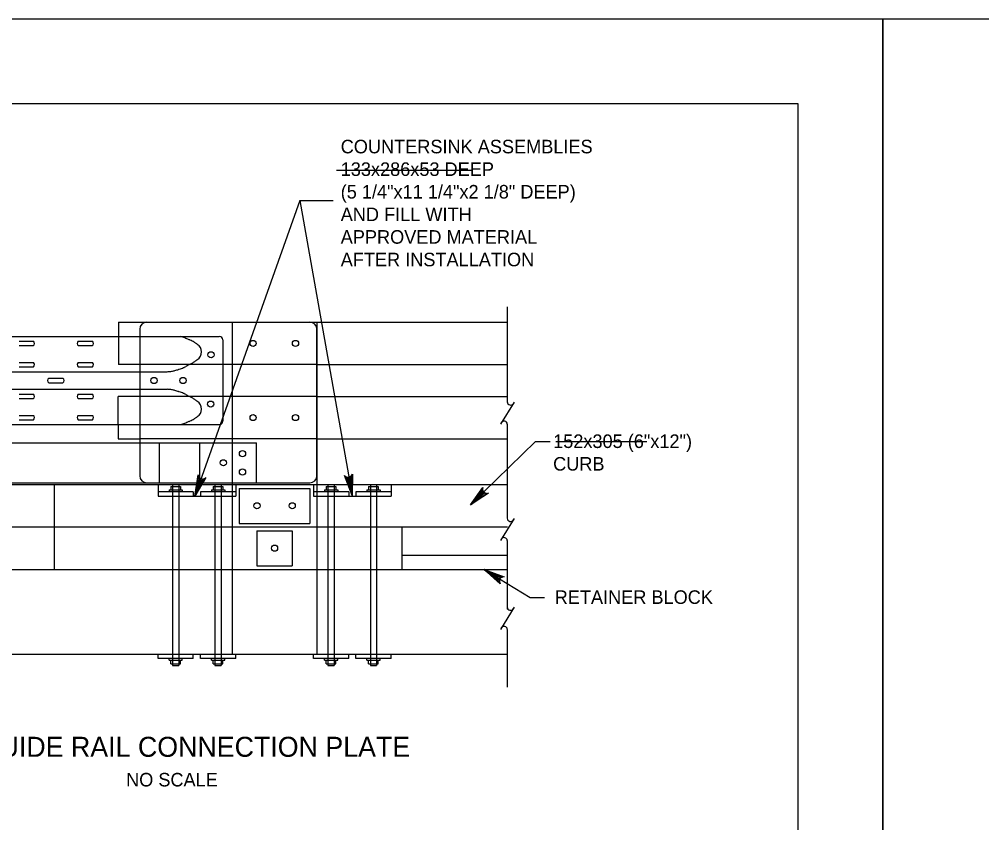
# Model space of a CAD drawing. Extents: x 179 to 454, y -271 to 54.
# Drawn here: x 387.12 to 395.64, y -7.11 to 0 of the extents above; entities that cross this region are included whole.
import ezdxf

# ---------------------------------------------------------------- set-up
doc = ezdxf.new("R2010")
doc.units = 0
for name, color, linetype in [('Level 1', 7, 'Continuous'), ('Level 2', 7, 'Continuous'), ('Level 3', 7, 'Continuous'), ('Level 41', 7, 'Continuous'), ('Level 52', 7, 'Continuous'), ('Level 62', 7, 'Continuous'), ('Level 63', 7, 'Continuous')]:
    doc.layers.add(name, color=color, linetype=linetype)

msp = doc.modelspace()

# ---------------------------------------------------------------- linework, layer by layer
at = {"layer": 'Level 1'}
msp.add_lwpolyline([(362.5132, -21.25), (394.0132, -21.25), (394.0132, -0.75), (362.5132, -0.75)], close=True, dxfattribs=at)
at = {"layer": 'Level 2'}
for p, q in [((391.4403, -2.5474), (391.4403, -3.3866)), ((388.0011, -2.6827), (390.048, -2.6827)), ((389.0062, -2.6827), (389.0062, -3.0577)), ((389.7562, -2.6827), (389.7562, -3.0577)), ((390.048, -2.6827), (391.4422, -2.6827)), ((387.0486, -2.8077), (388.8923, -2.8077)), ((388.001, -2.8077), (388.001, -3.0577)), ((388.1886, -2.7452), (388.1886, -3.5889)), ((387.1222, -2.8507), (387.2472, -2.8507)), ((387.1222, -2.8897), (387.2472, -2.8897)), ((387.6443, -2.8507), (387.7693, -2.8507)), ((387.6443, -2.8897), (387.7693, -2.8897)), ((388.9236, -2.839), (388.9236, -3.5577)), ((387.1222, -3.0382), (387.2472, -3.0382)), ((387.6443, -3.0382), (387.7693, -3.0382)), ((389.7562, -3.0577), (388.001, -3.0577)), ((389.0062, -3.0577), (389.0062, -3.3389)), ((389.7562, -3.0577), (389.7562, -3.3389)), ((389.7562, -3.0577), (391.4422, -3.0577)), ((385.5172, -3.1202), (388.4303, -3.1202)), ((387.1222, -3.0772), (387.2472, -3.0772)), ((387.6443, -3.0772), (387.7693, -3.0772)), ((387.3827, -3.1788), (387.5077, -3.1788)), ((387.3827, -3.2178), (387.5077, -3.2178)), ((385.4967, -3.2764), (388.4303, -3.2764)), ((387.1222, -3.3194), (387.2472, -3.3194)), ((387.6443, -3.3194), (387.7693, -3.3194)), ((387.1222, -3.3585), (387.2472, -3.3585)), ((387.6443, -3.3585), (387.7693, -3.3585)), ((389.7562, -3.3389), (387.9967, -3.3389)), ((387.9967, -3.5889), (387.9967, -3.3389)), ((389.0062, -3.3389), (389.0062, -3.7139)), ((389.7562, -3.3389), (389.7562, -3.7139)), ((389.7562, -3.3389), (391.4422, -3.3389)), ((391.5017, -3.3888), (391.3789, -3.5844)), ((387.1222, -3.5069), (387.2472, -3.5069)), ((387.1222, -3.546), (387.2472, -3.546)), ((387.6443, -3.5069), (387.7693, -3.5069)), ((387.6443, -3.546), (387.7693, -3.546)), ((385.4967, -3.5889), (388.8923, -3.5889)), ((387.9967, -3.5889), (387.9967, -3.7139)), ((388.1886, -3.5889), (388.1886, -4.0414)), ((391.4403, -3.584), (391.4403, -4.4181)), ((387.9967, -3.7139), (388.1886, -3.7139)), ((389.7562, -3.7139), (388.1885, -3.7139)), ((389.0062, -3.7139), (389.0062, -4.2217)), ((389.7562, -3.7139), (389.7562, -4.2217)), ((389.7562, -3.7139), (391.4422, -3.7139)), ((385.2677, -3.7502), (389.2222, -3.7502)), ((389.7562, -3.9997), (389.7562, -4.1202)), ((385.2677, -4.1039), (389.6937, -4.1039)), ((386.2928, -4.1202), (391.4422, -4.1202)), ((387.4317, -4.1202), (387.4317, -4.8702)), ((387.5406, -4.1202), (391.222, -4.1202)), ((388.3499, -4.1202), (388.3499, -4.2217)), ((388.4476, -4.167), (388.4476, -4.1827)), ((388.4476, -4.167), (388.5648, -4.167)), ((388.4632, -4.1357), (388.4632, -4.167)), ((388.4632, -4.1357), (388.5492, -4.1357)), ((388.4788, -4.1202), (388.5335, -4.1202)), ((388.4788, -4.1202), (388.4788, -5.7217)), ((388.5335, -4.1202), (388.5335, -5.7217)), ((388.5492, -4.1357), (388.5492, -4.167)), ((388.5648, -4.167), (388.5648, -4.1827)), ((388.8226, -4.167), (388.8226, -4.1827)), ((388.8226, -4.167), (388.9398, -4.167)), ((388.8382, -4.1357), (388.9242, -4.1357)), ((388.8382, -4.1357), (388.8382, -4.167)), ((388.8538, -4.1202), (388.9085, -4.1202)), ((388.8538, -4.1202), (388.8538, -5.7217)), ((388.9085, -4.1202), (388.9085, -5.7217)), ((388.9242, -4.1357), (388.9242, -4.167)), ((388.9398, -4.167), (388.9398, -4.1827)), ((389.0062, -4.1039), (389.0062, -4.1202)), ((389.0374, -4.1202), (389.0374, -4.2217)), ((389.0687, -4.1537), (389.6937, -4.1537)), ((389.0687, -4.1537), (389.0687, -4.4639)), ((389.0687, -4.1538), (389.6937, -4.1538)), ((389.6937, -4.1537), (389.6937, -4.4639)), ((389.7249, -4.1202), (389.7249, -4.2217)), ((389.7562, -4.1039), (389.7562, -4.1697)), ((389.8226, -4.167), (389.8226, -4.1827)), ((389.8226, -4.167), (389.9398, -4.167)), ((389.8382, -4.1357), (389.9242, -4.1357)), ((389.8382, -4.1357), (389.8382, -4.167)), ((389.8538, -4.1202), (389.9085, -4.1202)), ((389.8538, -4.1202), (389.8538, -5.7217)), ((389.9085, -4.1202), (389.9085, -5.7217)), ((389.9242, -4.1357), (389.9242, -4.167)), ((389.9398, -4.167), (389.9398, -4.1827)), ((390.1976, -4.167), (390.1976, -4.1827)), ((390.1976, -4.167), (390.3148, -4.167)), ((390.2132, -4.1357), (390.2992, -4.1357)), ((390.2132, -4.1357), (390.2132, -4.167)), ((390.2288, -4.1202), (390.2835, -4.1202)), ((390.2288, -4.1202), (390.2288, -5.7217)), ((390.2835, -4.1202), (390.2835, -5.7217)), ((390.2992, -4.1357), (390.2992, -4.167)), ((390.3148, -4.167), (390.3148, -4.1827)), ((390.4124, -4.1202), (390.4124, -4.2217)), ((388.6624, -4.1827), (388.3499, -4.1827)), ((388.3499, -4.2217), (389.0374, -4.2217)), ((388.6624, -4.1827), (388.6624, -4.2217)), ((389.0374, -4.1827), (388.7249, -4.1827)), ((388.7249, -4.1827), (388.7249, -4.2217)), ((389.0062, -4.2217), (389.0062, -5.6201)), ((390.0374, -4.1827), (389.7249, -4.1827)), ((389.7249, -4.2217), (390.4124, -4.2217)), ((389.7562, -4.2217), (389.7562, -5.6201)), ((390.0374, -4.1827), (390.0374, -4.2217)), ((390.4124, -4.1827), (390.0999, -4.1827)), ((390.0999, -4.1827), (390.0999, -4.2217)), ((391.5017, -4.4203), (391.3789, -4.6159)), ((386.2928, -4.4952), (391.4422, -4.4952)), ((389.0687, -4.4639), (389.6937, -4.4639)), ((390.5062, -4.4952), (390.5062, -4.8702)), ((389.225, -4.5287), (389.225, -4.8389)), ((389.225, -4.5287), (389.5375, -4.5287)), ((389.5375, -4.5287), (389.5375, -4.8389)), ((391.4403, -4.6156), (391.4403, -5.2228)), ((390.5062, -4.7452), (391.4422, -4.7452)), ((389.225, -4.8389), (389.5375, -4.8389)), ((386.2928, -4.8702), (391.4422, -4.8702)), ((391.5017, -5.2059), (391.3789, -5.4015)), ((391.4403, -5.4023), (391.4403, -5.9131)), ((386.2928, -5.6201), (391.4422, -5.6201)), ((388.3499, -5.6592), (388.3499, -5.6201)), ((388.6624, -5.6592), (388.6624, -5.6201)), ((388.7249, -5.6592), (388.7249, -5.6201)), ((389.0374, -5.6592), (389.0374, -5.6201)), ((389.7249, -5.6592), (389.7249, -5.6201)), ((390.0374, -5.6592), (390.0374, -5.6201)), ((390.0999, -5.6592), (390.0999, -5.6201)), ((390.4124, -5.6592), (390.4124, -5.6201)), ((388.6624, -5.6592), (388.3499, -5.6592)), ((388.4476, -5.6748), (388.4476, -5.6592)), ((388.4476, -5.6748), (388.5648, -5.6748)), ((388.4632, -5.7061), (388.4632, -5.6748)), ((388.5492, -5.7061), (388.5492, -5.6748)), ((388.5648, -5.6748), (388.5648, -5.6592)), ((389.0374, -5.6592), (388.7249, -5.6592)), ((388.8226, -5.6748), (388.8226, -5.6592)), ((388.8226, -5.6748), (388.9398, -5.6748)), ((388.8382, -5.7061), (388.8382, -5.6748)), ((388.9242, -5.7061), (388.9242, -5.6748)), ((388.9398, -5.6748), (388.9398, -5.6592)), ((390.0374, -5.6592), (389.7249, -5.6592)), ((389.8226, -5.6748), (389.8226, -5.6592)), ((389.8226, -5.6748), (389.9398, -5.6748)), ((389.8382, -5.7061), (389.8382, -5.6748)), ((389.9242, -5.7061), (389.9242, -5.6748)), ((389.9398, -5.6748), (389.9398, -5.6592)), ((390.4124, -5.6592), (390.0999, -5.6592)), ((390.1976, -5.6748), (390.1976, -5.6592)), ((390.1976, -5.6748), (390.3148, -5.6748)), ((390.2132, -5.7061), (390.2132, -5.6748)), ((390.2992, -5.7061), (390.2992, -5.6748)), ((390.3148, -5.6748), (390.3148, -5.6592)), ((388.4632, -5.7061), (388.5492, -5.7061)), ((388.4788, -5.7217), (388.5335, -5.7217)), ((388.8382, -5.7061), (388.9242, -5.7061)), ((388.8538, -5.7217), (388.9085, -5.7217)), ((389.8382, -5.7061), (389.9242, -5.7061)), ((389.8538, -5.7217), (389.9085, -5.7217)), ((390.2132, -5.7061), (390.2992, -5.7061)), ((390.2288, -5.7217), (390.2835, -5.7217))]:
    msp.add_line(p, q, dxfattribs=at)
for centre in [(389.1912, -2.8702), (389.5663, -2.8702), (388.8193, -2.9709), (388.314, -3.1983), (388.571, -3.1983), (388.8162, -3.4071), (389.1912, -3.5265), (389.5663, -3.5265), (389.0974, -3.8464), (388.9283, -3.927), (389.0974, -4.0077), (389.225, -4.3076), (389.5375, -4.3076), (389.3812, -4.6826)]:
    msp.add_circle(centre, 0.0273, dxfattribs=at)
for centre, radius, start, end in [((388.251, -2.7452), 0.0625, 90, 180), ((388.2969, -3.6302), 0.8602, 71.50655, 72.97663), ((388.8923, -2.839), 0.0312, 0, 90), ((387.2355, -2.8702), 0.0228, 300.85592, 59.14408), ((387.656, -2.8702), 0.0228, 120.85592, 239.14408), ((387.7576, -2.8702), 0.0228, 300.85592, 59.14408), ((388.5192, -2.9656), 0.1594, 68.09066, 71.50655), ((386.536, -7.8966), 5.4742, 67.68511, 68.09066), ((388.4241, -3.2963), 0.5016, 66.34532, 67.68511), ((388.5434, -3.0241), 0.2044, 63.42506, 66.34532), ((387.4315, -5.2469), 2.6898, 62.62019, 63.42506), ((388.6313, -2.9302), 0.0808, 54.67713, 62.62019), ((388.4621, -3.169), 0.3735, 50.98486, 54.67712), ((388.6581, -2.9456), 0.0775, 301.3851, 59.64679), ((387.2355, -3.0577), 0.0228, 300.85592, 59.14408), ((387.656, -3.0577), 0.0228, 120.85592, 239.14408), ((387.7576, -3.0577), 0.0228, 300.85592, 59.14408), ((393.2769, -11.608), 9.733, 118.56505, 118.75012), ((393.7331, -12.4459), 10.6871, 118.47252, 118.56505), ((372.799, 26.154), 33.224, 298.47252, 298.525), ((388.621, -2.9561), 0.092, 298.525, 306.88177), ((388.4254, -2.6954), 0.4179, 306.88177, 310.79926), ((388.4106, -2.6951), 0.4255, 272.64288, 278.36698), ((388.446, -2.9355), 0.1825, 278.36698, 287.11147), ((386.2113, 4.3233), 7.7775, 287.11147, 287.36106), ((388.4527, -2.8462), 0.2658, 287.36106, 288.71113), ((388.0449, -1.6421), 1.5372, 288.71113, 290.23288), ((388.5576, -3.0333), 0.0545, 290.23288, 298.32146), ((387.7228, -1.4842), 1.8143, 298.32146, 298.75012), ((387.3943, -3.1983), 0.0228, 120.85592, 239.14408), ((387.496, -3.1983), 0.0228, 300.85592, 59.14408), ((387.2355, -3.339), 0.0228, 300.85592, 59.14408), ((387.656, -3.339), 0.0228, 120.85592, 239.14408), ((387.7576, -3.339), 0.0228, 300.85592, 59.14408), ((388.4106, -3.7015), 0.4255, 81.63302, 87.35713), ((388.446, -3.4611), 0.1825, 72.88853, 81.63302), ((386.2113, -10.7199), 7.7775, 72.63894, 72.88853), ((388.4527, -3.5504), 0.2658, 71.28887, 72.63894), ((388.0449, -4.7546), 1.5372, 69.76712, 71.28887), ((388.5576, -3.3634), 0.0545, 61.67854, 69.76712), ((387.7228, -4.9125), 1.8143, 61.24988, 61.67854), ((393.2769, 5.2113), 9.733, 241.24988, 241.43495), ((393.7331, 6.0493), 10.6871, 241.43495, 241.52748), ((372.799, -32.5506), 33.224, 61.475, 61.52748), ((388.621, -3.4405), 0.092, 53.11823, 61.475), ((388.4254, -3.7012), 0.4179, 49.20074, 53.11823), ((388.6581, -3.451), 0.0775, 300.35321, 58.61491), ((391.4691, -3.3866), 0.0289, 180, 330), ((387.2355, -3.5265), 0.0228, 300.85592, 59.14408), ((387.656, -3.5265), 0.0228, 120.85592, 239.14408), ((387.7576, -3.5265), 0.0228, 300.85592, 59.14408), ((386.536, 1.4999), 5.4742, 291.90934, 292.31489), ((388.4241, -3.1003), 0.5016, 292.31489, 293.65468), ((388.5434, -3.3726), 0.2044, 293.65468, 296.57494), ((387.4315, -1.1498), 2.6898, 296.57494, 297.37981), ((388.6313, -3.4665), 0.0808, 297.37981, 305.32288), ((388.4621, -3.2276), 0.3735, 305.32288, 309.01514), ((388.8923, -3.5577), 0.0312, 270, 0), ((391.4115, -3.5867), 0.0289, 5.32859, 147.86724), ((388.2969, -2.7665), 0.8602, 287.02337, 288.49345), ((388.5192, -3.4311), 0.1594, 288.49345, 291.90934), ((388.251, -4.0414), 0.0625, 180, 270), ((389.6937, -4.0414), 0.0625, 270, 0), ((391.4691, -4.4181), 0.0289, 180, 330), ((391.4115, -4.6182), 0.0289, 5.32859, 147.86724), ((391.4691, -5.2037), 0.0289, 180, 330), ((391.4115, -5.4037), 0.0289, 5.32859, 147.86724)]:
    msp.add_arc(centre, radius, start, end, dxfattribs=at)
at = {"layer": 'Level 3'}
for p, q in [((389.6041, -1.606), (388.6769, -4.2217)), ((389.6041, -1.606), (389.8982, -1.606)), ((389.6041, -1.606), (390.0679, -4.2164)), ((388.0011, -2.6827), (388.0011, -2.8077)), ((389.7562, -4.0414), (389.7562, -2.7452)), ((388.3642, -4.1039), (388.3642, -3.7502)), ((388.7209, -4.1039), (388.7209, -3.7502)), ((389.2222, -4.1039), (389.2222, -3.7502))]:
    msp.add_line(p, q, dxfattribs=at)
for points in [[(388.677, -4.2217), (388.7063, -4.0343), (388.7109, -4.0512), (388.7202, -4.0623), (388.7312, -4.0685), (388.7437, -4.0707), (388.758, -4.0678), (388.7722, -4.0577), (388.677, -4.2217), (388.758, -4.0678), (388.7437, -4.0707), (388.677, -4.2217), (388.7312, -4.0685), (388.7202, -4.0623), (388.677, -4.2217), (388.7109, -4.0512)], [(390.0679, -4.2164), (390.0009, -4.039), (390.0132, -4.0514), (390.0268, -4.0565), (390.0395, -4.0564), (390.0514, -4.0521), (390.0624, -4.0427), (390.0697, -4.0267), (390.0679, -4.2164), (390.0624, -4.0427), (390.0514, -4.0521), (390.0679, -4.2164), (390.0395, -4.0564), (390.0268, -4.0565), (390.0679, -4.2164), (390.0132, -4.0514)]]:
    msp.add_lwpolyline(points, dxfattribs=at)
msp.add_arc((389.6937, -2.7452), 0.0625, 0, 90, dxfattribs=at)
at = {"layer": 'Level 41'}
for p, q in [((389.9278, -1.3361), (391.1346, -1.3361)), ((391.8697, -3.7374), (392.6742, -3.7374))]:
    msp.add_line(p, q, dxfattribs=at)
at = {"layer": 'Level 52'}
for points in [[(391.1151, -4.3003), (391.6898, -3.7387), (391.8183, -3.7387)], [(391.1151, -4.3003), (391.224, -4.145), (391.2207, -4.1622), (391.2242, -4.1763), (391.2313, -4.1867), (391.2416, -4.1942), (391.2557, -4.1979), (391.2728, -4.195), (391.1151, -4.3003), (391.2557, -4.1979), (391.2416, -4.1942), (391.1151, -4.3003), (391.2313, -4.1867), (391.2242, -4.1763), (391.1151, -4.3003), (391.2207, -4.1622)], [(391.2368, -4.8702), (391.6425, -5.119), (391.7709, -5.119)], [(391.2368, -4.8702), (391.414, -4.9378), (391.3966, -4.9388), (391.3837, -4.9456), (391.3753, -4.9552), (391.3706, -4.9669), (391.3704, -4.9814), (391.3774, -4.9974), (391.2368, -4.8702), (391.3704, -4.9814), (391.3706, -4.9669), (391.2368, -4.8702), (391.3753, -4.9552), (391.3837, -4.9456), (391.2368, -4.8702), (391.3966, -4.9388)]]:
    msp.add_lwpolyline(points, dxfattribs=at)
at = {"layer": 'Level 62'}
msp.add_line((394.7633, 0), (394.7633, 0), dxfattribs=at)
at = {"layer": 'Level 63'}
for points in [[(360.7633, -22), (394.7633, -22), (394.7633, 0), (360.7633, 0)], [(394.7633, -22), (428.7633, -22), (428.7633, 0), (394.7633, 0)]]:
    msp.add_lwpolyline(points, close=True, dxfattribs=at)

# ---------------------------------------------------------------- texts
at = {"layer": 'Level 2'}
msp.add_text('VIEW A @ 15.9 (5/8") GUIDE RAIL CONNECTION PLATE', height=0.177167, dxfattribs=at).set_placement((384.3981, -6.5297))
at = {"layer": 'Level 3'}
for s, p in [('COUNTERSINK ASSEMBLIES', (389.9664, -1.1872)), ('133x286x53 DEEP', (389.9664, -1.3872)), ('(5 1/4"x11 1/4"x2 1/8" DEEP)', (389.9664, -1.5873)), ('AND FILL WITH', (389.9664, -1.7873)), ('APPROVED MATERIAL', (389.9664, -1.9872)), ('AFTER INSTALLATION', (389.9664, -2.1873)), ('152x305 (6"x12")', (391.8458, -3.7959)), ('CURB', (391.8458, -3.9959)), ('RETAINER BLOCK', (391.8597, -5.176)), ('NO SCALE', (388.0675, -6.7923))]:
    msp.add_text(s, height=0.12, dxfattribs=at).set_placement(p)

doc.saveas('drawing.dxf')
